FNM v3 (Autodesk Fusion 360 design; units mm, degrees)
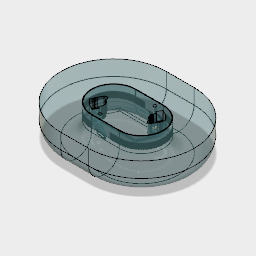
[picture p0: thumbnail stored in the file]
sketch "スケッチ1"
  circle C1 centre (50, 0) radius 190
  circle C2 centre (-50, 0) radius 190
  circle C3 centre (-50, 0) radius 80
  circle C4 centre (50, 0) radius 80
  circle C5 centre (50, 0) radius 78
  circle C6 centre (-50, 0) radius 78
  tangent C1
  tangent C1
  tangent C2
  tangent C2
  concentric C2 C3
  concentric C1 C4
  tangent C4
  tangent C3
  tangent C4
  concentric C4 C5
  concentric C3 C6
  tangent C5
  tangent C6
  tangent C3
  tangent C5
  dimension "d1" distance = 380
  dimension "d2" distance = 100
  dimension "d5" distance = 110
  dimension "d11" distance = 2
extrude "押し出し1" sketch "スケッチ1" blind -100
fillet "フィレット" radius 54.9999
extrude "押し出し4" sketch "スケッチ1" blind -33
work_plane "作業平面1" AlongDistance -33
base_feature "基準フィーチャ1"
base_feature "基準フィーチャ1"
copy_paste_bodies "CopyPasteBodies1"
step "ボディを移動1"
copy_paste_bodies "CopyPasteBodies2"
step "ボディを移動2"
base_feature "基準フィーチャ1"
combine "結合7"
combine "結合3"
step "ボディを移動3"
step "ボディを移動4"
step "ボディを移動5"
extrude "押し出し8" of existing geometry blind 30
extrude "押し出し9" of existing geometry blind 25
extrude "押し出し10" of existing geometry blind 25
extrude "押し出し11" of existing geometry blind 28
work_plane "作業平面3" AlongDistance 0
extrude "押し出し12" of existing geometry blind -2
delete_face "面を削除3"
combine "結合4"
delete_face "面を削除4"
delete_face "面を削除6"
offset_faces "面をオフセット2" distance 25
step "ボディを移動7"
sketch "スケッチ7"
  circle C1 centre (-50, 0) radius 78
  circle C2 centre (50, 0) radius 78
  circle C3 centre (-74.7233, 28) radius 16
  tangent C3
  coincident C3
  tangent C3
  dimension "d41" radius C3 = 16
  dimension "d30" distance = 70
  dimension "d32" angle = 115
  dimension "d40" distance = 63
  dimension "d42" distance = 9
extrude "押し出し13" sketch "スケッチ7" blind 10
work_plane "作業平面5" AlongDistance 0
sketch "スケッチ10"
  dimension "d64" angle = 90
  dimension "d65" distance = 2
  dimension "d67" distance = 10
  dimension "d72" distance = 75
extrude "押し出し14" sketch "スケッチ10" blind 20
sketch "スケッチ11"
  dimension "d71" distance = 80
circular_pattern "C パターン4" countU 60 TotalAngle -180
rectangular_pattern "R パターン" uSpaceDistance 32 vSpaceDistance 0
circular_pattern "C パターン5" TotalAngle 360
combine "結合15"
delete_face "面を削除10"
combine "結合8"
combine "結合9"
delete_face "面を削除7"
extrude "押し出し15" of existing geometry blind -1.5
delete_face "面を削除9"
extrude "押し出し17" of existing geometry blind 7.5
circular_pattern "C パターン6" TotalAngle 360
combine "結合10"
combine "結合11"
combine "結合12"
combine "結合14"
offset_faces "面をオフセット4" distance 10
component_from_bodies "ボディ -> コンポーネント4"
component_from_bodies "ボディ -> コンポーネント5"
component_from_bodies "ボディ -> コンポーネント6"
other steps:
base_feature "基準フィーチャ1"
base_feature "基準フィーチャ1"
base_feature "基準フィーチャ1"
base_feature "基準フィーチャ1"
base_feature "基準フィーチャ2"
create_component "CreateComponent7"
create_component "CreateComponent8"
create_component "CreateComponent10"
remove_body "RemoveBody1"
create_component "CreateComponent11"
remove_body "RemoveBody4"
create_component "CreateComponent12"
remove_body "RemoveBody5"
create_component "CreateComponent13"
remove_body "RemoveBody6"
